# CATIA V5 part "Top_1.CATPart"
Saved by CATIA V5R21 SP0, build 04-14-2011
Part number: Part1.7
Material "DS Yellow": density 7860 kg/m3, Young's modulus 2e+11 Pa, Poisson ratio 0.266
Bounding box of the stored display mesh (mm): x 0 to 30, y -10 to 10, z -10 to 10
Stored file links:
  C:\Users\RIAD MAHAMUD PIASH\Desktop\Project\Top_1.CATPart
  C:\Program Files (x86)\Dassault Systemes\B21\intel_a\startup\materials\yellow_env_512x512.jpg
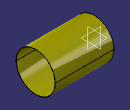
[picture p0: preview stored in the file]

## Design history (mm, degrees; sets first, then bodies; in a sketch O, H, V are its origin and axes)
Body1 (main body), material "DS Yellow"
  Sketch1 on yz-plane, origin (0, 0, 0), H (0, 1, 0), V (0, 0, 1)
    circle A1 centre (0, 0) radius 10
    circle A2 centre (0, 0) radius 9.9
    radius A2 = 9.9
    radius A1 = 10
  Pad1: profile Sketch1, direction (1, 0, 0), length 30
